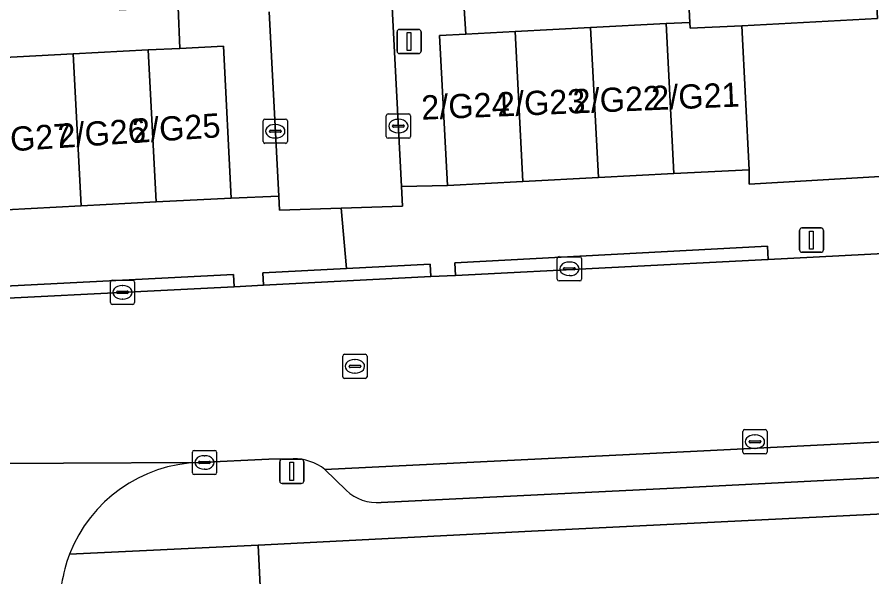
# Model space of a CAD drawing. Extents: x 161084 to 161928, y 385354 to 386522.
# Drawn here: x 161389.16 to 161424.42, y 385436.63 to 385459.74 of the extents above; entities that cross this region are included whole.
import ezdxf

# ---------------------------------------------------------------- set-up
doc = ezdxf.new("R2010")
doc.units = 0
for name, color, linetype in [('IMGEO_Erf', 7, 'Continuous'), ('IMGEO_Kolk', 7, 'Continuous'), ('IMGEO_Lichtmast', 7, 'Continuous'), ('IMGEO_Pand', 7, 'Continuous'), ('IMGEO_Pand_nummerreeks', 7, 'Continuous'), ('IMGEO_Parkeervlak_open', 7, 'Continuous'), ('IMGEO_Rijbaan_lokaal_open', 7, 'Continuous'), ('IMGEO_Rioolput', 7, 'Continuous'), ('IMGEO_Voetpad_open', 7, 'Continuous')]:
    doc.layers.add(name, color=color, linetype=linetype)

msp = doc.modelspace()

# ---------------------------------------------------------------- linework, layer by layer
at = {"layer": 'IMGEO_Erf'}
for points in [[(161425.182, 385526.476), (161421.216, 385526.254), (161421.535, 385520.062), (161421.846, 385514.041), (161422.156, 385508.02), (161422.467, 385501.999), (161422.57, 385500), (161422.777, 385495.978), (161423.088, 385489.958), (161423.399, 385483.937), (161423.709, 385477.916), (161424.02, 385471.895), (161424.33, 385465.874), (161424.65, 385459.679), (161419.05, 385459.388), (161419.359, 385453.441), (161419.358, 385452.841), (161429.459, 385453.441)], [(161406.331, 385484.996), (161406.529, 385481.207), (161408.997, 385481.329), (161409.204, 385477.166), (161409.411, 385472.989), (161406.943, 385472.867), (161407.079, 385469.098), (161409.574, 385469.24), (161409.808, 385465.124), (161410.049, 385460.885), (161407.554, 385460.743), (161407.671, 385459.044), (161409.7, 385459.15), (161412.813, 385459.311), (161415.925, 385459.473), (161416.902, 385459.524), (161416.6, 385465.475), (161416.294, 385471.496), (161415.989, 385477.517), (161415.683, 385483.538), (161415.378, 385489.56)], [(161388.381, 385458.064), (161391.476, 385458.224), (161394.572, 385458.384), (161395.872, 385458.451), (161395.808, 385460.155), (161393.401, 385460.025), (161393.175, 385464.215), (161392.946, 385468.444), (161395.353, 385468.574), (161395.205, 385472.174), (161392.788, 385472.027), (161392.529, 385476.271), (161392.27, 385480.529), (161394.687, 385480.676), (161394.502, 385484.379)], [(161531.457, 385435.246), (161530.957, 385444.578), (161522.121, 385444.14), (161514.172, 385443.782), (161506.893, 385443.442), (161489.826, 385442.609), (161472.328, 385441.714), (161462.435, 385441.214), (161462.607, 385437.07), (161459.521, 385436.942), (161459.349, 385441.056), (161451.84, 385440.651), (161445.994, 385440.367), (161427.695, 385439.377), (161410.372, 385438.518), (161399.098, 385437.94), (161399.975, 385420.149)]]:
    msp.add_lwpolyline(points, dxfattribs=at)
at = {"layer": 'IMGEO_Kolk'}
for p, q in [((161404.387, 385454.816), (161404.387, 385455.668)), ((161404.462, 385455.742), (161405.314, 385455.742)), ((161405.388, 385455.668), (161405.388, 385454.816)), ((161399.308, 385454.605), (161399.308, 385455.457)), ((161399.383, 385455.531), (161400.235, 385455.531)), ((161399.796, 385455.311), (161399.821, 385455.311)), ((161400.309, 385455.457), (161400.309, 385454.605)), ((161404.646, 385455.236), (161404.646, 385455.248)), ((161404.689, 385455.285), (161405.087, 385455.285)), ((161404.875, 385455.522), (161404.9, 385455.522)), ((161405.13, 385455.248), (161405.13, 385455.236)), ((161399.567, 385455.025), (161399.567, 385455.037)), ((161400.005, 385454.988), (161399.607, 385454.988)), ((161399.61, 385455.074), (161400.008, 385455.074)), ((161400.051, 385455.037), (161400.051, 385455.025)), ((161405.084, 385455.199), (161404.686, 385455.199)), ((161404.898, 385454.962), (161404.873, 385454.962)), ((161399.819, 385454.751), (161399.794, 385454.751)), ((161405.314, 385454.742), (161404.462, 385454.742)), ((161400.235, 385454.531), (161399.383, 385454.531)), ((161411.441, 385448.926), (161411.441, 385449.778)), ((161411.516, 385449.852), (161412.368, 385449.852)), ((161411.929, 385449.632), (161411.954, 385449.632)), ((161412.442, 385449.778), (161412.442, 385448.926)), ((161411.7, 385449.346), (161411.7, 385449.358)), ((161412.138, 385449.309), (161411.74, 385449.309)), ((161411.743, 385449.395), (161412.141, 385449.395)), ((161412.184, 385449.358), (161412.184, 385449.346)), ((161411.952, 385449.072), (161411.927, 385449.072)), ((161393.007, 385447.954), (161393.007, 385448.806)), ((161393.082, 385448.88), (161393.934, 385448.88)), ((161393.495, 385448.66), (161393.52, 385448.66)), ((161394.008, 385448.806), (161394.008, 385447.954)), ((161412.368, 385448.852), (161411.516, 385448.852)), ((161393.266, 385448.374), (161393.266, 385448.386)), ((161393.704, 385448.337), (161393.306, 385448.337)), ((161393.309, 385448.423), (161393.707, 385448.423)), ((161393.75, 385448.386), (161393.75, 385448.374)), ((161393.934, 385447.88), (161393.082, 385447.88)), ((161393.518, 385448.1), (161393.493, 385448.1)), ((161419.091, 385441.785), (161419.091, 385442.637)), ((161419.166, 385442.711), (161420.018, 385442.711)), ((161420.092, 385442.637), (161420.092, 385441.785)), ((161419.35, 385442.205), (161419.35, 385442.217)), ((161419.393, 385442.254), (161419.791, 385442.254)), ((161419.579, 385442.491), (161419.604, 385442.491)), ((161419.834, 385442.217), (161419.834, 385442.205)), ((161396.464, 385441.856), (161397.316, 385441.856)), ((161419.788, 385442.168), (161419.39, 385442.168)), ((161419.602, 385441.931), (161419.577, 385441.931)), ((161396.389, 385440.93), (161396.389, 385441.782)), ((161396.877, 385441.636), (161396.902, 385441.636)), ((161397.39, 385441.782), (161397.39, 385440.93)), ((161420.018, 385441.711), (161419.166, 385441.711)), ((161396.648, 385441.35), (161396.648, 385441.362)), ((161397.086, 385441.313), (161396.688, 385441.313)), ((161396.691, 385441.399), (161397.089, 385441.399)), ((161397.132, 385441.362), (161397.132, 385441.35)), ((161397.316, 385440.856), (161396.464, 385440.856)), ((161396.9, 385441.076), (161396.875, 385441.076))]:
    msp.add_line(p, q, dxfattribs=at)
for points in [[(161404.387, 385454.816), (161404.387, 385455.668)], [(161404.462, 385455.742), (161405.314, 385455.742)], [(161405.388, 385455.668), (161405.388, 385454.816)], [(161399.308, 385454.605), (161399.308, 385455.457)], [(161399.383, 385455.531), (161400.235, 385455.531)], [(161400.309, 385455.457), (161400.309, 385454.605)], [(161405.314, 385454.742), (161404.462, 385454.742)], [(161400.235, 385454.531), (161399.383, 385454.531)], [(161411.441, 385448.926), (161411.441, 385449.778)], [(161411.516, 385449.852), (161412.368, 385449.852)], [(161412.442, 385449.778), (161412.442, 385448.926)], [(161393.007, 385447.954), (161393.007, 385448.806)], [(161393.082, 385448.88), (161393.934, 385448.88)], [(161394.008, 385448.806), (161394.008, 385447.954)], [(161412.368, 385448.852), (161411.516, 385448.852)], [(161393.934, 385447.88), (161393.082, 385447.88)], [(161419.091, 385441.785), (161419.091, 385442.637)], [(161419.166, 385442.711), (161420.018, 385442.711)], [(161420.092, 385442.637), (161420.092, 385441.785)], [(161396.464, 385441.856), (161397.316, 385441.856)], [(161396.389, 385440.93), (161396.389, 385441.782)], [(161397.39, 385441.782), (161397.39, 385440.93)], [(161420.018, 385441.711), (161419.166, 385441.711)], [(161397.316, 385440.856), (161396.464, 385440.856)]]:
    msp.add_lwpolyline(points, dxfattribs=at)
for centre, radius, start, end in [((161404.464, 385455.666), 0.0765, 91.552, 178.448), ((161404.464, 385455.666), 0.0765, 91.552, 178.448), ((161405.312, 385455.666), 0.0765, 1.552, 88.448), ((161405.312, 385455.666), 0.0765, 1.552, 88.448), ((161399.385, 385455.455), 0.0765, 91.552, 178.448), ((161399.385, 385455.455), 0.0765, 91.552, 178.448), ((161400.233, 385455.455), 0.0765, 1.552, 88.448), ((161400.233, 385455.455), 0.0765, 1.552, 88.448), ((161404.686, 385455.245), 0.0403, 85.8775, 175.7526), ((161405.091, 385455.247), 0.0386, 1.7309, 96.639), ((161399.607, 385455.034), 0.0403, 85.8775, 175.7526), ((161399.604, 385455.024), 0.0366, 178.938, 274.7102), ((161400.008, 385455.031), 0.043, 264.8664, 352.4533), ((161400.012, 385455.036), 0.0386, 1.7309, 96.639), ((161404.683, 385455.235), 0.0366, 178.938, 274.7102), ((161405.087, 385455.242), 0.043, 264.8664, 352.4533), ((161399.385, 385454.607), 0.0765, 181.552, 268.448), ((161399.385, 385454.607), 0.0765, 181.552, 268.448), ((161400.233, 385454.607), 0.0765, 271.552, 358.448), ((161400.233, 385454.607), 0.0765, 271.552, 358.448), ((161404.464, 385454.818), 0.0765, 181.552, 268.448), ((161404.464, 385454.818), 0.0765, 181.552, 268.448), ((161405.312, 385454.818), 0.0765, 271.552, 358.448), ((161405.312, 385454.818), 0.0765, 271.552, 358.448), ((161411.518, 385449.776), 0.0765, 91.552, 178.448), ((161411.518, 385449.776), 0.0765, 91.552, 178.448), ((161412.366, 385449.776), 0.0765, 1.552, 88.448), ((161412.366, 385449.776), 0.0765, 1.552, 88.448), ((161411.74, 385449.355), 0.0403, 85.8775, 175.7526), ((161411.737, 385449.345), 0.0366, 178.938, 274.7102), ((161412.141, 385449.352), 0.043, 264.8664, 352.4533), ((161412.145, 385449.357), 0.0386, 1.7309, 96.639), ((161411.518, 385448.928), 0.0765, 181.552, 268.448), ((161411.518, 385448.928), 0.0765, 181.552, 268.448), ((161412.366, 385448.928), 0.0765, 271.552, 358.448), ((161412.366, 385448.928), 0.0765, 271.552, 358.448), ((161393.084, 385448.804), 0.0765, 91.552, 178.448), ((161393.084, 385448.804), 0.0765, 91.552, 178.448), ((161393.932, 385448.804), 0.0765, 1.552, 88.448), ((161393.932, 385448.804), 0.0765, 1.552, 88.448), ((161393.306, 385448.383), 0.0403, 85.8775, 175.7526), ((161393.303, 385448.373), 0.0366, 178.938, 274.7102), ((161393.707, 385448.38), 0.043, 264.8664, 352.4533), ((161393.711, 385448.385), 0.0386, 1.7309, 96.639), ((161393.084, 385447.956), 0.0765, 181.552, 268.448), ((161393.084, 385447.956), 0.0765, 181.552, 268.448), ((161393.932, 385447.956), 0.0765, 271.552, 358.448), ((161393.932, 385447.956), 0.0765, 271.552, 358.448), ((161419.168, 385442.635), 0.0765, 91.552, 178.448), ((161419.168, 385442.635), 0.0765, 91.552, 178.448), ((161420.016, 385442.635), 0.0765, 1.552, 88.448), ((161420.016, 385442.635), 0.0765, 1.552, 88.448), ((161419.39, 385442.214), 0.0403, 85.8775, 175.7526), ((161419.387, 385442.204), 0.0366, 178.938, 274.7102), ((161419.791, 385442.211), 0.043, 264.8664, 352.4533), ((161419.795, 385442.216), 0.0386, 1.7309, 96.639), ((161396.466, 385441.78), 0.0765, 91.552, 178.448), ((161396.466, 385441.78), 0.0765, 91.552, 178.448), ((161397.314, 385441.78), 0.0765, 1.552, 88.448), ((161397.314, 385441.78), 0.0765, 1.552, 88.448), ((161419.168, 385441.787), 0.0765, 181.552, 268.448), ((161419.168, 385441.787), 0.0765, 181.552, 268.448), ((161420.016, 385441.787), 0.0765, 271.552, 358.448), ((161420.016, 385441.787), 0.0765, 271.552, 358.448), ((161396.688, 385441.359), 0.0403, 85.8775, 175.7526), ((161396.685, 385441.349), 0.0366, 178.938, 274.7102), ((161397.089, 385441.356), 0.043, 264.8664, 352.4533), ((161397.093, 385441.361), 0.0386, 1.7309, 96.639), ((161396.466, 385440.932), 0.0765, 181.552, 268.448), ((161396.466, 385440.932), 0.0765, 181.552, 268.448), ((161397.314, 385440.932), 0.0765, 271.552, 358.448), ((161397.314, 385440.932), 0.0765, 271.552, 358.448)]:
    msp.add_arc(centre, radius, start, end, dxfattribs=at)
for centre, major_axis, ratio, start_param, end_param in [((161399.795, 385455.031), (-0.387, 0.002), 0.722429, 4.712389, 7.853982), ((161399.82, 385455.031), (-0.39, 0.002), 0.717154, 1.570796, 4.712389), ((161404.874, 385455.242), (-0.387, 0.002), 0.722429, 4.712389, 7.853982), ((161404.899, 385455.242), (-0.39, 0.002), 0.717154, 1.570796, 4.712389), ((161411.928, 385449.352), (-0.387, 0.002), 0.722429, 4.712389, 7.853982), ((161411.953, 385449.352), (-0.39, 0.002), 0.717154, 1.570796, 4.712389), ((161393.494, 385448.38), (-0.387, 0.002), 0.722429, 4.712389, 7.853982), ((161393.519, 385448.38), (-0.39, 0.002), 0.717154, 1.570796, 4.712389), ((161419.578, 385442.211), (-0.387, 0.002), 0.722429, 4.712389, 7.853982), ((161419.603, 385442.211), (-0.39, 0.002), 0.717154, 1.570796, 4.712389), ((161396.876, 385441.356), (-0.387, 0.002), 0.722429, 4.712389, 7.853982), ((161396.901, 385441.356), (-0.39, 0.002), 0.717154, 1.570796, 4.712389)]:
    msp.add_ellipse(centre, major_axis=major_axis, ratio=ratio, start_param=start_param, end_param=end_param, dxfattribs=at)
at = {"layer": 'IMGEO_Lichtmast'}
for p, q in [((161404.831, 385458.334), (161404.831, 385459.134)), ((161404.831, 385459.134), (161404.831, 385458.334)), ((161404.931, 385459.234), (161405.721, 385459.234)), ((161405.721, 385459.234), (161404.931, 385459.234)), ((161405.821, 385459.134), (161405.821, 385458.334)), ((161405.821, 385458.334), (161405.821, 385459.134)), ((161405.721, 385458.234), (161404.931, 385458.234)), ((161404.931, 385458.234), (161405.721, 385458.234)), ((161421.529, 385451.036), (161422.319, 385451.036)), ((161422.319, 385451.036), (161421.529, 385451.036)), ((161421.429, 385450.136), (161421.429, 385450.936)), ((161421.429, 385450.936), (161421.429, 385450.136)), ((161422.419, 385450.936), (161422.419, 385450.136)), ((161422.419, 385450.136), (161422.419, 385450.936)), ((161422.319, 385450.036), (161421.529, 385450.036)), ((161421.529, 385450.036), (161422.319, 385450.036)), ((161399.993, 385440.588), (161399.993, 385441.388)), ((161399.993, 385441.388), (161399.993, 385440.588)), ((161400.093, 385441.488), (161400.883, 385441.488)), ((161400.883, 385441.488), (161400.093, 385441.488)), ((161400.983, 385441.388), (161400.983, 385440.588)), ((161400.983, 385440.588), (161400.983, 385441.388)), ((161400.883, 385440.488), (161400.093, 385440.488)), ((161400.093, 385440.488), (161400.883, 385440.488))]:
    msp.add_line(p, q, dxfattribs=at)
for points in [[(161405.251, 385459.109), (161405.401, 385459.109), (161405.401, 385458.359), (161405.251, 385458.359), (161405.251, 385459.109)], [(161421.849, 385450.911), (161421.999, 385450.911), (161421.999, 385450.161), (161421.849, 385450.161), (161421.849, 385450.911)], [(161400.413, 385441.363), (161400.563, 385441.363), (161400.563, 385440.613), (161400.413, 385440.613), (161400.413, 385441.363)]]:
    msp.add_lwpolyline(points, dxfattribs=at)
for centre, start, end in [((161404.931, 385459.134), 90, 180), ((161404.931, 385459.134), 90, 180), ((161405.721, 385459.134), 0, 90), ((161405.721, 385459.134), 360, 90), ((161404.931, 385458.334), 180, 270), ((161404.931, 385458.334), 180, 270), ((161405.721, 385458.334), 270, 0), ((161405.721, 385458.334), 270, 0), ((161421.529, 385450.936), 90, 180), ((161421.529, 385450.936), 90, 180), ((161422.319, 385450.936), 0, 90), ((161422.319, 385450.936), 360, 90), ((161421.529, 385450.136), 180, 270), ((161421.529, 385450.136), 180, 270), ((161422.319, 385450.136), 270, 0), ((161422.319, 385450.136), 270, 0), ((161400.093, 385441.388), 90, 180), ((161400.093, 385441.388), 90, 180), ((161400.883, 385441.388), 0, 90), ((161400.883, 385441.388), 360, 90), ((161400.093, 385440.588), 180, 270), ((161400.093, 385440.588), 180, 270), ((161400.883, 385440.588), 270, 0), ((161400.883, 385440.588), 270, 0)]:
    msp.add_arc(centre, 0.1, start, end, dxfattribs=at)
at = {"layer": 'IMGEO_Pand'}
for points in [[(161416.914, 385459.279), (161419.05, 385459.388), (161424.65, 385459.679), (161424.33, 385465.874), (161416.6, 385465.475), (161416.902, 385459.524)], [(161415.925, 385459.473), (161412.813, 385459.311), (161413.134, 385453.118), (161416.247, 385453.279)], [(161419.359, 385453.441), (161419.05, 385459.388), (161416.914, 385459.279), (161416.902, 385459.524), (161415.925, 385459.473), (161416.247, 385453.279)], [(161406.588, 385458.988), (161406.91, 385452.794), (161410.022, 385452.956), (161409.7, 385459.15), (161407.671, 385459.044)], [(161410.022, 385452.956), (161413.134, 385453.118), (161412.813, 385459.311), (161409.7, 385459.15)], [(161397.668, 385458.544), (161395.872, 385458.451), (161394.572, 385458.384), (161394.896, 385452.112), (161397.992, 385452.272)], [(161391.476, 385458.224), (161388.381, 385458.064), (161388.706, 385451.791), (161391.801, 385451.952)], [(161391.801, 385451.952), (161394.896, 385452.112), (161394.572, 385458.384), (161391.476, 385458.224)]]:
    msp.add_lwpolyline(points, close=True, dxfattribs=at)
at = {"layer": 'IMGEO_Parkeervlak_open'}
for points in [[(161429.859, 385442.449), (161417.213, 385441.82), (161401.854, 385441.064), (161402.728, 385440.207)], [(161404.174, 385439.704), (161416.234, 385440.298), (161427.286, 385440.857), (161429.944, 385441.001), (161429.859, 385442.449)]]:
    msp.add_lwpolyline(points, dxfattribs=at)
msp.add_arc((161404.02, 385441.592), 1.894, 226.978, 274.6609, dxfattribs=at)
at = {"layer": 'IMGEO_Rijbaan_lokaal_open'}
for points in [[(161405.017, 385452.752), (161404.623, 385460.419)], [(161399.561, 385459.962), (161399.952, 385452.344)], [(161429.402, 385450.214), (161420.142, 385449.74), (161407.241, 385449.079), (161406.226, 385449.027), (161399.328, 385448.674), (161398.109, 385448.611), (161384.362, 385447.912), (161382.433, 385448.035), (161356.06, 385452.696), (161354.803, 385445.84), (161379.871, 385441.275), (161396.667, 385441.355), (161399.543, 385441.489), (161400.55, 385441.508)], [(161402.52, 385451.855), (161405.059, 385451.938), (161405.017, 385452.752)], [(161399.952, 385452.344), (161399.981, 385451.772), (161402.52, 385451.855)], [(161401.854, 385441.064), (161417.213, 385441.82), (161429.859, 385442.449), (161429.402, 385450.214)], [(161396.667, 385441.355), (161379.871, 385441.275)]]:
    msp.add_lwpolyline(points, dxfattribs=at)
for centre, radius, start, end in [((161400.597, 385439.51), 1.999, 51.0417, 91.3518), ((161396.844, 385435.446), 5.912, 91.7155, 158.9611), ((161396.834, 385435.443), 5.904, 158.9071, 183.7412)]:
    msp.add_arc(centre, radius, start, end, dxfattribs=at)
at = {"layer": 'IMGEO_Rioolput'}
for p, q in [((161402.593, 385444.898), (161402.593, 385445.75)), ((161402.668, 385445.824), (161403.52, 385445.824)), ((161403.594, 385445.75), (161403.594, 385444.898)), ((161402.895, 385445.367), (161403.293, 385445.367)), ((161403.081, 385445.604), (161403.106, 385445.604)), ((161402.852, 385445.318), (161402.852, 385445.33)), ((161403.29, 385445.281), (161402.892, 385445.281)), ((161403.104, 385445.044), (161403.079, 385445.044)), ((161403.336, 385445.33), (161403.336, 385445.318)), ((161403.52, 385444.824), (161402.668, 385444.824))]:
    msp.add_line(p, q, dxfattribs=at)
for points in [[(161402.593, 385444.898), (161402.593, 385445.75)], [(161402.668, 385445.824), (161403.52, 385445.824)], [(161403.594, 385445.75), (161403.594, 385444.898)], [(161403.52, 385444.824), (161402.668, 385444.824)]]:
    msp.add_lwpolyline(points, dxfattribs=at)
for centre, radius, start, end in [((161402.67, 385445.748), 0.0765, 91.552, 178.448), ((161402.67, 385445.748), 0.0765, 91.552, 178.448), ((161403.518, 385445.748), 0.0765, 1.552, 88.448), ((161403.518, 385445.748), 0.0765, 1.552, 88.448), ((161402.892, 385445.327), 0.0403, 85.8775, 175.7526), ((161403.297, 385445.329), 0.0386, 1.7309, 96.639), ((161402.889, 385445.317), 0.0366, 178.938, 274.7102), ((161403.293, 385445.324), 0.043, 264.8664, 352.4533), ((161402.67, 385444.9), 0.0765, 181.552, 268.448), ((161402.67, 385444.9), 0.0765, 181.552, 268.448), ((161403.518, 385444.9), 0.0765, 271.552, 358.448), ((161403.518, 385444.9), 0.0765, 271.552, 358.448)]:
    msp.add_arc(centre, radius, start, end, dxfattribs=at)
for centre, major_axis, ratio, start_param, end_param in [((161403.08, 385445.324), (-0.387, 0.002), 0.722429, 4.712389, 7.853982), ((161403.105, 385445.324), (-0.39, 0.002), 0.717154, 1.570796, 4.712389)]:
    msp.add_ellipse(centre, major_axis=major_axis, ratio=ratio, start_param=start_param, end_param=end_param, dxfattribs=at)
at = {"layer": 'IMGEO_Voetpad_open'}
for points in [[(161404.623, 385460.419), (161405.017, 385452.752), (161406.91, 385452.794), (161406.588, 385458.988), (161407.671, 385459.044), (161407.554, 385460.743), (161407.312, 385464.996), (161407.079, 385469.098), (161406.943, 385472.867), (161406.736, 385477.039), (161406.529, 385481.207), (161406.331, 385484.996)], [(161394.502, 385484.379), (161394.687, 385480.676), (161394.948, 385476.397), (161395.205, 385472.174), (161395.353, 385468.574), (161395.582, 385464.341), (161395.808, 385460.155), (161395.872, 385458.451), (161397.668, 385458.544), (161397.992, 385452.272), (161399.952, 385452.344), (161399.561, 385459.962)], [(161327.794, 385457.821), (161353.24, 385453.143), (161356.06, 385452.696), (161382.433, 385448.035), (161384.362, 385447.912), (161384.335, 385448.411), (161398.082, 385449.119), (161398.109, 385448.611), (161399.328, 385448.674), (161399.301, 385449.182), (161402.75, 385449.364), (161402.52, 385451.855), (161399.981, 385451.772), (161399.952, 385452.344), (161397.992, 385452.272), (161394.896, 385452.112), (161391.801, 385451.952), (161388.706, 385451.791), (161385.61, 385451.631), (161385.727, 385450.238), (161380.981, 385451.115)], [(161429.459, 385453.441), (161419.358, 385452.841), (161419.359, 385453.441), (161416.247, 385453.279), (161413.134, 385453.118), (161410.022, 385452.956), (161406.91, 385452.794), (161405.017, 385452.752), (161405.059, 385451.938), (161402.52, 385451.855), (161402.75, 385449.364), (161406.198, 385449.545), (161406.226, 385449.027), (161407.241, 385449.079), (161407.212, 385449.6), (161420.111, 385450.292), (161420.142, 385449.74), (161429.402, 385450.214)], [(161391.326, 385437.568), (161399.098, 385437.94), (161410.372, 385438.518), (161427.695, 385439.377), (161445.994, 385440.367), (161445.878, 385443.299), (161445.036, 385443.271)], [(161400.55, 385441.508), (161399.543, 385441.489), (161396.667, 385441.355)], [(161442.368, 385441.672), (161432.725, 385441.151), (161429.944, 385441.001), (161427.286, 385440.857), (161416.234, 385440.298), (161404.174, 385439.704)], [(161402.728, 385440.207), (161401.854, 385441.064)], [(161399.098, 385437.94), (161391.326, 385437.568)], [(161393.049, 385432.688), (161396.433, 385432.891), (161397.095, 385420.031), (161399.975, 385420.149), (161399.098, 385437.94)]]:
    msp.add_lwpolyline(points, dxfattribs=at)
for points in [[(161407.241, 385449.079), (161420.142, 385449.74), (161420.111, 385450.292), (161407.212, 385449.6)], [(161406.198, 385449.545), (161402.75, 385449.364), (161399.301, 385449.182), (161399.328, 385448.674), (161406.226, 385449.027)], [(161384.362, 385447.912), (161398.109, 385448.611), (161398.082, 385449.119), (161384.335, 385448.411)]]:
    msp.add_lwpolyline(points, close=True, dxfattribs=at)
for centre, radius, start, end in [((161400.597, 385439.51), 1.999, 51.0417, 91.3518), ((161396.844, 385435.446), 5.912, 91.7155, 158.9611), ((161404.02, 385441.592), 1.894, 226.978, 274.6609), ((161396.834, 385435.443), 5.904, 158.9071, 183.7412)]:
    msp.add_arc(centre, radius, start, end, dxfattribs=at)

# ---------------------------------------------------------------- texts
at = {"layer": 'IMGEO_Pand_nummerreeks'}
for s, rotation, p in [('2/G21', 2.3859, (161415.338, 385455.899)), ('2/G23', 2.3859, (161408.978, 385455.634)), ('2/G22', 2.3859, (161412.096, 385455.764)), ('2/G24', 2.3859, (161405.853, 385455.504)), ('2/G25', 3.8785, (161393.942, 385454.539)), ('2/G27', 3.8785, (161387.796, 385454.123)), ('2/G26', 3.8785, (161390.869, 385454.331))]:
    msp.add_text(s, height=1, rotation=rotation, dxfattribs=at).set_placement(p)

doc.saveas('drawing.dxf')
